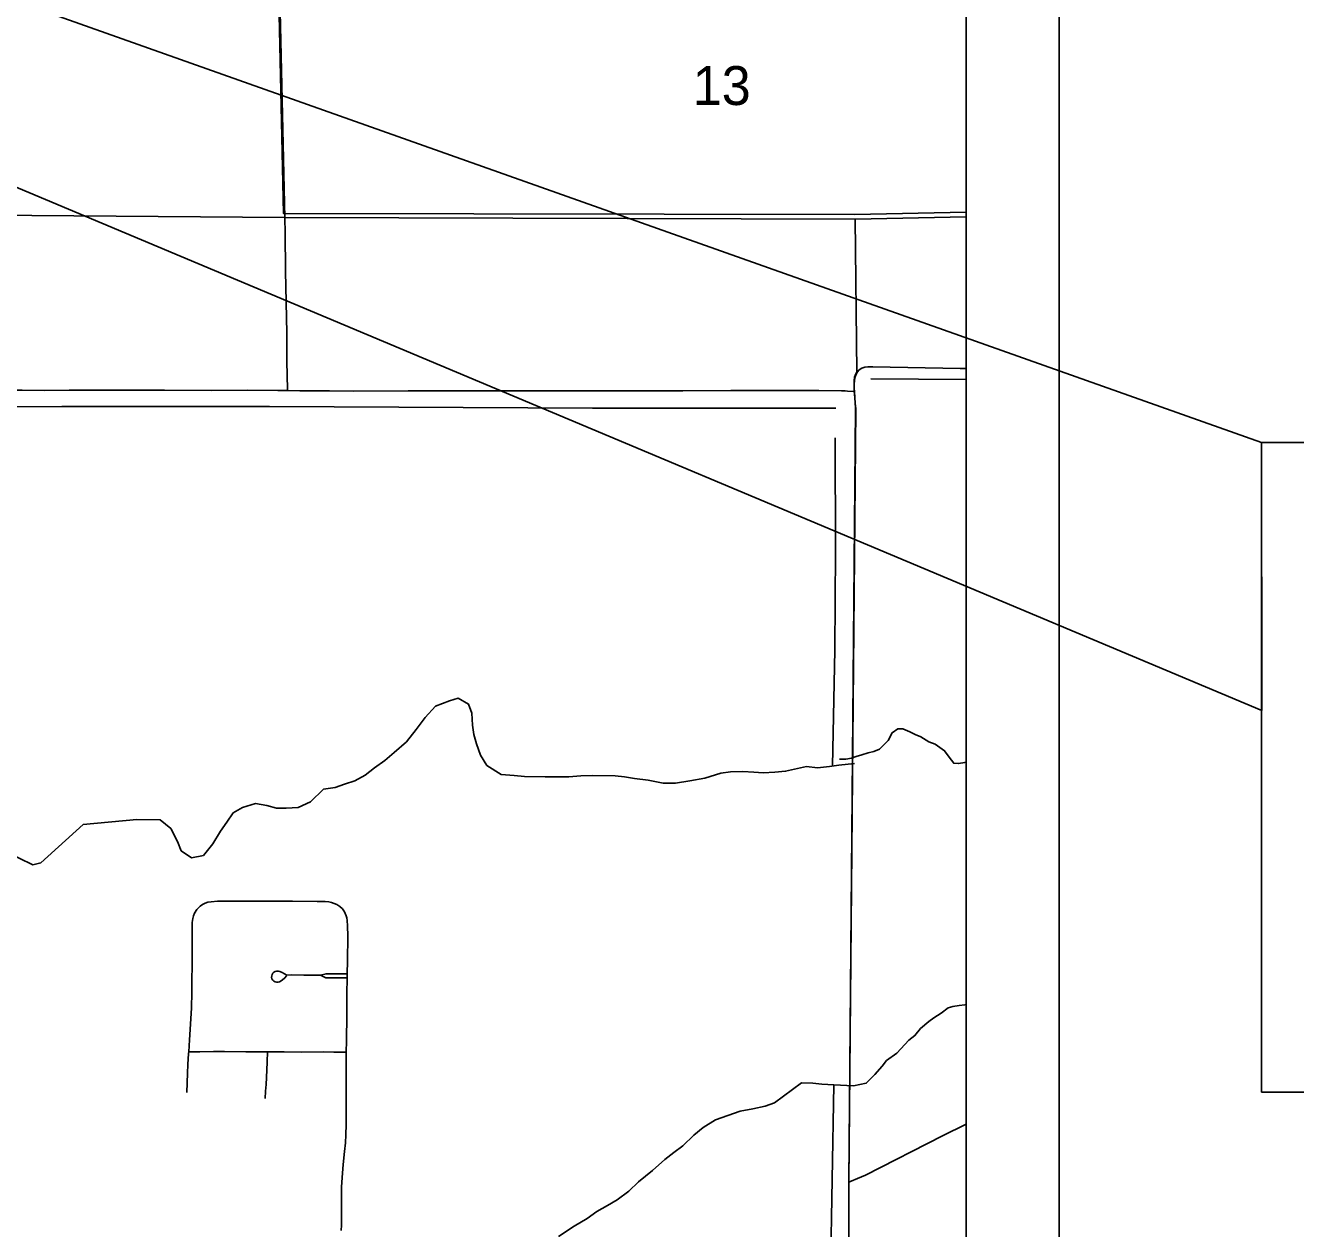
# Model space of a CAD drawing. Extents: x 0 to 40.2, y 0 to 22.
# Drawn here: x 7.889 to 9.254, y 16.354 to 17.647 of the extents above; entities that cross this region are included whole.
import ezdxf

# ---------------------------------------------------------------- set-up
doc = ezdxf.new("R2010")
doc.units = 0
for name, color, linetype in [('GM_X_Adjacent_County', 7, 'Continuous'), ('GM_X_City_Street', 7, 'Continuous'), ('GM_X_Corporation', 7, 'Continuous'), ('GM_X_Major_Lake_Text', 7, 'Continuous'), ('GM_X_Minor_Lake', 7, 'Continuous'), ('GM_X_Rail_Line', 7, 'Continuous'), ('GM_X_Section', 7, 'Continuous'), ('GM_X_Township_Road', 7, 'Continuous'), ('GM_X_Unincorporated_Location', 7, 'Continuous')]:
    doc.layers.add(name, color=color, linetype=linetype)

msp = doc.modelspace()

# ---------------------------------------------------------------- linework, layer by layer
at = {"layer": 'GM_X_Adjacent_County'}
for p, q in [((9, 21), (9, 14)), ((8.9, 20.9), (8.9, 14.1))]:
    msp.add_line(p, q, dxfattribs=at)
at = {"layer": 'GM_X_Corporation'}
for points in [[(6.1544, 17.4248), (6.5609, 17.4286), (7.8499, 17.4434), (8.1678, 17.4407), (8.7809, 17.439), (8.9, 17.4415), (8.9, 20.9)], [(6.1544, 17.4248), (6.5609, 17.4286), (7.8499, 17.4434), (8.1678, 17.4407), (8.7809, 17.439), (8.9, 17.4415), (8.9, 20.9)], [(6.1544, 17.4248), (6.5609, 17.4286), (7.8499, 17.4434), (8.1678, 17.4407), (8.7809, 17.439), (8.9, 17.4415), (8.9, 20.9)], [(8.7738, 16.2476), (8.7739, 16.404), (8.7812, 17.2357), (8.7808, 17.2416), (8.7804, 17.2472), (8.7798, 17.254), (8.7797, 17.2579), (8.7797, 17.2625), (8.7798, 17.2656), (8.7803, 17.2689), (8.7813, 17.272), (8.7828, 17.2749), (8.7809, 17.439), (8.1678, 17.4407), (7.8499, 17.4434), (6.5609, 17.4286), (6.1544, 17.4248)], [(8.7738, 16.2476), (8.7739, 16.404), (8.7812, 17.2357), (8.7808, 17.2416), (8.7804, 17.2472), (8.7798, 17.254), (8.7797, 17.2579), (8.7797, 17.2625), (8.7798, 17.2656), (8.7803, 17.2689), (8.7813, 17.272), (8.7828, 17.2749), (8.7809, 17.439), (8.1678, 17.4407), (7.8499, 17.4434), (6.5609, 17.4286), (6.1544, 17.4248)], [(8.7738, 16.2476), (8.7739, 16.404), (8.7812, 17.2357), (8.7808, 17.2416), (8.7804, 17.2472), (8.7798, 17.254), (8.7797, 17.2579), (8.7797, 17.2625), (8.7798, 17.2656), (8.7803, 17.2689), (8.7813, 17.272), (8.7828, 17.2749), (8.7809, 17.439), (8.1678, 17.4407), (7.8499, 17.4434), (6.5609, 17.4286), (6.1544, 17.4248)], [(8.9, 14.1), (8.9, 17.4415), (8.7809, 17.439), (8.7828, 17.2749), (8.7813, 17.272), (8.7803, 17.2689), (8.7798, 17.2656), (8.7797, 17.2625), (8.7797, 17.2579), (8.7798, 17.254), (8.7804, 17.2472), (8.7808, 17.2416), (8.7812, 17.2357), (8.7739, 16.404), (8.7738, 16.2476)], [(8.9, 14.1), (8.9, 17.4415), (8.7809, 17.439), (8.7828, 17.2749), (8.7813, 17.272), (8.7803, 17.2689), (8.7798, 17.2656), (8.7797, 17.2625), (8.7797, 17.2579), (8.7798, 17.254), (8.7804, 17.2472), (8.7808, 17.2416), (8.7812, 17.2357), (8.7739, 16.404), (8.7738, 16.2476)]]:
    msp.add_lwpolyline(points, dxfattribs=at)
msp.add_lwpolyline([(8.9, 17.4466), (8.9, 17.7526), (8.1599, 17.7413), (8.1663, 17.4452), (8.7803, 17.4441)], close=True, dxfattribs=at)
at = {"layer": 'GM_X_Major_Lake_Text'}
for p, q in [((8.168, 17.4401), (8.1611, 17.7324)), ((8.7741, 16.2471), (8.7742, 16.4035))]:
    msp.add_line(p, q, dxfattribs=at)
for points in [[(8.78, 17.2535), (8.7799, 17.2573), (8.7799, 17.2619), (8.78, 17.2651), (8.7805, 17.2683), (8.7815, 17.2714), (8.783, 17.2743)], [(8.7742, 16.4035), (8.7815, 17.2351), (8.781, 17.2411), (8.7806, 17.2467), (8.78, 17.2535)]]:
    msp.add_lwpolyline(points, dxfattribs=at)
at = {"layer": 'GM_X_Minor_Lake'}
msp.add_line((8.7978, 17.2673), (8.9, 17.2665), dxfattribs=at)
for points in [[(8.7602, 17.2356), (8.4984, 17.2357), (8.1515, 17.2375), (7.9283, 17.2376), (7.7978, 17.2367)], [(8.7564, 16.8511), (8.7591, 16.9754), (8.7596, 17.0816), (8.7593, 17.2038)], [(8.78, 16.8536), (8.7632, 16.852), (8.7533, 16.8506), (8.7404, 16.8489), (8.7287, 16.8503), (8.7189, 16.8482), (8.706, 16.8453), (8.6946, 16.8444), (8.6821, 16.8438), (8.6719, 16.8444), (8.6602, 16.8449), (8.6469, 16.8448), (8.6363, 16.8434), (8.6192, 16.838), (8.6033, 16.8352), (8.5877, 16.8324), (8.5745, 16.8327), (8.5583, 16.8356), (8.5435, 16.8377), (8.533, 16.8394), (8.5228, 16.8403), (8.4989, 16.8407), (8.4861, 16.8405), (8.4732, 16.8392), (8.4607, 16.8394), (8.4475, 16.8393), (8.4255, 16.8396), (8.4142, 16.8406), (8.4002, 16.8419), (8.3849, 16.8517), (8.3782, 16.8628), (8.3739, 16.875), (8.371, 16.8849), (8.3697, 16.8948), (8.3687, 16.9077), (8.3651, 16.9176), (8.3542, 16.9239), (8.3447, 16.921), (8.3299, 16.9155), (8.3187, 16.9032), (8.3091, 16.8901), (8.2986, 16.8769), (8.2852, 16.8654), (8.2752, 16.8568), (8.2641, 16.8491), (8.2542, 16.8412), (8.2431, 16.835), (8.2321, 16.8314), (8.2218, 16.8277), (8.2093, 16.826), (8.1955, 16.8126), (8.1821, 16.8064), (8.1693, 16.8058), (8.159, 16.8056), (8.1485, 16.8084), (8.1364, 16.8105), (8.1223, 16.8062), (8.1124, 16.8007), (8.1055, 16.7905), (8.0985, 16.7808), (8.0903, 16.7672), (8.0803, 16.7549), (8.0674, 16.7521), (8.0565, 16.7598), (8.0525, 16.7698), (8.0452, 16.7839), (8.034, 16.7932), (8.0087, 16.7936)], [(8.8269, 16.8909), (8.8208, 16.8867), (8.8162, 16.8783), (8.8071, 16.8692), (8.8011, 16.8666), (8.795, 16.865), (8.7882, 16.8631), (8.7821, 16.8612), (8.7768, 16.8593), (8.7707, 16.8582), (8.7642, 16.8582)], [(8.9, 16.855), (8.8986, 16.8548), (8.8921, 16.8536), (8.8868, 16.854), (8.8819, 16.8605), (8.8769, 16.8673), (8.8667, 16.8745), (8.8602, 16.8768), (8.8515, 16.8825), (8.8454, 16.8848), (8.8398, 16.8878), (8.8322, 16.8909), (8.8269, 16.8909)], [(8.0087, 16.7936), (7.9511, 16.7881), (7.9054, 16.7467), (7.897, 16.7449), (7.8674, 16.7591)], [(8.9, 16.5945), (8.8989, 16.5942), (8.8928, 16.5934), (8.886, 16.5923), (8.8807, 16.5911), (8.8734, 16.5854), (8.8655, 16.5801), (8.8602, 16.5763), (8.8511, 16.5687), (8.845, 16.5611), (8.8385, 16.5562), (8.8256, 16.5421), (8.8146, 16.5345), (8.8099, 16.5284), (8.8019, 16.5192), (8.7927, 16.5099), (8.779, 16.507)], [(8.779, 16.507), (8.7581, 16.508), (8.7452, 16.5089), (8.7354, 16.5099), (8.7233, 16.5104), (8.6942, 16.4889), (8.6843, 16.4853), (8.6707, 16.4824), (8.6574, 16.48), (8.6308, 16.4706), (8.6174, 16.4624), (8.6074, 16.4539), (8.5955, 16.4427), (8.5859, 16.4353), (8.5764, 16.4278), (8.5629, 16.4159), (8.548, 16.404), (8.5376, 16.3939), (8.525, 16.3846), (8.5147, 16.3784), (8.5032, 16.3721), (8.4929, 16.3643), (8.4788, 16.3562), (8.4619, 16.3451)], [(8.7581, 16.508), (8.7545, 16.3047), (8.7554, 16.1483), (8.7593, 15.9624), (8.7615, 15.8576)]]:
    msp.add_lwpolyline(points, dxfattribs=at)
at = {"layer": 'GM_X_Rail_Line'}
for points in [[(8.1708, 17.2547), (8.1707, 17.2579), (8.1704, 17.2691), (8.1701, 17.2881), (8.1698, 17.3164), (8.1686, 17.3832), (8.1682, 17.4242), (8.168, 17.4401)], [(8.783, 17.2743), (8.7852, 17.2768), (8.788, 17.2787), (8.7911, 17.2798), (8.7943, 17.2801), (8.7998, 17.2801), (8.8938, 17.2784), (8.9, 17.2784)], [(7.7778, 17.2551), (7.7817, 17.2552), (7.8227, 17.2552), (7.8532, 17.255), (7.8856, 17.255), (7.9098, 17.2549), (7.9359, 17.255), (7.9583, 17.255), (8.0385, 17.2552), (8.0895, 17.2549), (8.1281, 17.2551), (8.1604, 17.2548), (8.1708, 17.2547)], [(8.1708, 17.2547), (8.184, 17.2544), (8.1977, 17.2543), (8.2157, 17.2542), (8.2412, 17.2541), (8.3003, 17.2542), (8.3165, 17.2542), (8.3967, 17.2543), (8.4557, 17.2543), (8.5129, 17.2544), (8.5279, 17.2542), (8.567, 17.2545), (8.5956, 17.2545), (8.6473, 17.2547), (8.7231, 17.2548), (8.7418, 17.2548), (8.7663, 17.2545), (8.7701, 17.2542), (8.7728, 17.2541), (8.78, 17.2535)], [(8.7742, 16.4035), (8.7766, 16.4045), (8.7834, 16.4074), (8.7918, 16.4112), (8.8749, 16.4533), (8.9, 16.4659)]]:
    msp.add_lwpolyline(points, dxfattribs=at)
at = {"layer": 'GM_X_Section'}
for points in [[(9.2177, 17.1988), (9.2181, 16.9107), (4.8427, 18.7497)], [(9.2177, 17.1988), (11.0343, 17.1988), (11.0343, 16.5003), (9.2177, 16.5003)]]:
    msp.add_lwpolyline(points, close=True, dxfattribs=at)
at = {"layer": 'GM_X_Township_Road'}
msp.add_lwpolyline([(2.1, 20.9), (8.9, 20.9), (8.9, 14.1), (2.1, 14.1)], close=True, dxfattribs=at)
at = {"layer": 'GM_X_Unincorporated_Location'}
for points in [[(8.0733, 16.6968), (8.0746, 16.6982), (8.0768, 16.7003), (8.0794, 16.7021), (8.0821, 16.7035), (8.0851, 16.7045), (8.0888, 16.7051), (8.0955, 16.7057), (8.1033, 16.7058), (8.1143, 16.7058), (8.151, 16.7055), (8.1759, 16.7055), (8.2026, 16.7054), (8.2113, 16.7053), (8.215, 16.705), (8.2181, 16.7043), (8.221, 16.7033), (8.2238, 16.7019), (8.2269, 16.6998), (8.2299, 16.6973), (8.232, 16.6942)], [(8.0626, 16.4999), (8.0631, 16.5207), (8.0636, 16.5301), (8.0643, 16.5417), (8.0645, 16.5438), (8.0654, 16.5565), (8.0675, 16.5906), (8.0679, 16.6078), (8.068, 16.6183), (8.0681, 16.639), (8.0681, 16.6587), (8.0682, 16.6731), (8.0683, 16.6827), (8.0689, 16.687), (8.0696, 16.69), (8.0709, 16.6929), (8.0733, 16.6968)], [(8.2282, 16.3517), (8.2287, 16.3572), (8.2288, 16.3646), (8.2289, 16.3982), (8.2295, 16.4087), (8.2305, 16.4224), (8.2321, 16.4366), (8.2329, 16.4458), (8.2335, 16.4545), (8.2337, 16.4656), (8.2338, 16.483), (8.2339, 16.5134), (8.2339, 16.5352), (8.2339, 16.5389), (8.2339, 16.5432), (8.2341, 16.5556), (8.2342, 16.5618), (8.2344, 16.5768), (8.2344, 16.5873), (8.2346, 16.5997), (8.2346, 16.6059), (8.2348, 16.6231), (8.2349, 16.6277), (8.2351, 16.6414), (8.2355, 16.6681), (8.2353, 16.6792), (8.235, 16.6847), (8.2345, 16.6877), (8.2338, 16.69), (8.232, 16.6942)], [(8.1695, 16.6253), (8.1679, 16.6231), (8.165, 16.6207), (8.1622, 16.6191), (8.1606, 16.6186), (8.159, 16.6186), (8.1574, 16.6189), (8.156, 16.6197), (8.1548, 16.6208), (8.154, 16.6222), (8.1536, 16.6237), (8.1537, 16.6253), (8.1541, 16.6269), (8.1549, 16.6283), (8.1561, 16.6294), (8.1575, 16.6301), (8.1591, 16.6305), (8.1607, 16.6305), (8.1623, 16.6301), (8.1649, 16.629), (8.1675, 16.6275), (8.1699, 16.6262), (8.175, 16.6263), (8.1881, 16.6262), (8.2031, 16.6262), (8.2063, 16.6261)], [(8.2063, 16.6261), (8.2121, 16.6277), (8.2287, 16.6277), (8.2349, 16.6277)], [(8.2063, 16.6261), (8.2118, 16.6234), (8.2294, 16.6232), (8.2348, 16.6231)], [(8.0645, 16.5438), (8.0695, 16.5438), (8.0766, 16.5437), (8.0913, 16.544), (8.1031, 16.544), (8.126, 16.5437), (8.1491, 16.5437), (8.167, 16.5436), (8.1857, 16.5434), (8.2092, 16.5435), (8.2204, 16.5433), (8.2223, 16.5433), (8.2339, 16.5432)], [(8.1467, 16.4933), (8.1472, 16.5012), (8.1479, 16.5087), (8.1486, 16.5241), (8.1488, 16.5328), (8.1491, 16.5437)]]:
    msp.add_lwpolyline(points, dxfattribs=at)

# ---------------------------------------------------------------- texts
at = {"layer": 'GM_X_City_Street'}
msp.add_text('13', height=0.04186, rotation=0, dxfattribs=at).set_placement((8.6063, 17.5617))

doc.saveas('drawing.dxf')
